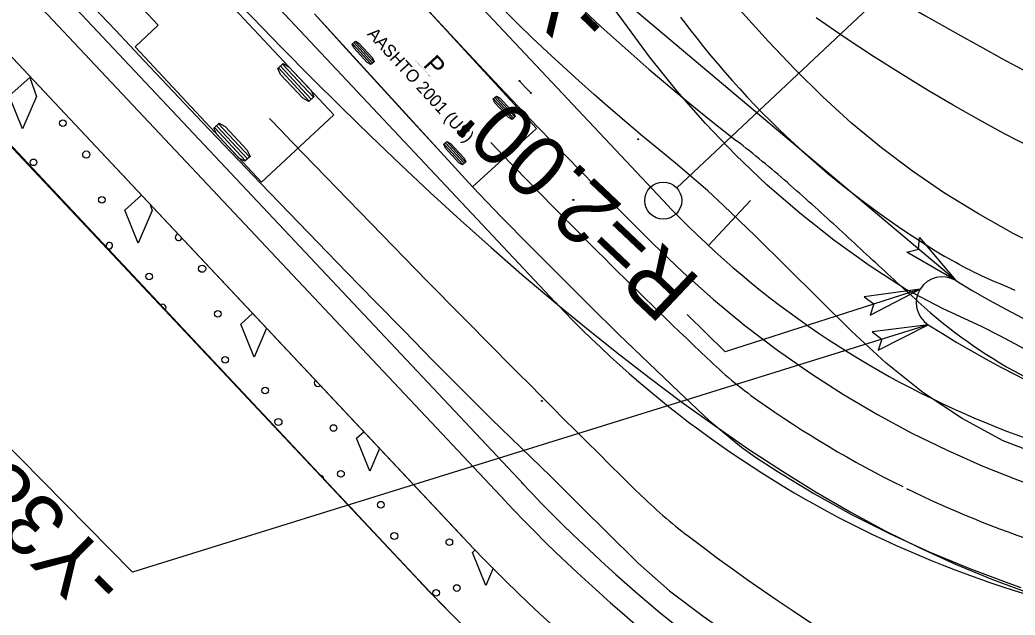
# Model space of a CAD drawing. Extents: x 1262642 to 1268358, y 767825 to 773481.
# Drawn here: x 1266608.5 to 1266689.1, y 772119 to 772167.3 of the extents above; entities that cross this region are included whole.
import ezdxf

# ---------------------------------------------------------------- set-up
doc = ezdxf.new("R2010")
doc.units = 0
for name, color, linetype in [('Prop Conc 2ft 6in Curb and Gutter', 7, 'Continuous'), ('Prop Conc 4in Sidewalk', 7, 'Continuous'), ('Prop Conc 5in Monolithic Keyed In Island', 7, 'Continuous'), ('Prop Dimension', 7, 'Continuous'), ('Prop Dimension Text', 7, 'Continuous'), ('Prop EOT', 7, 'Continuous'), ('Prop Horizontal Alignment', 7, 'Continuous'), ('Prop Horizontal Alignment Station Label', 7, 'Continuous'), ('Prop Horizontal Alignment Tick Small', 7, 'Continuous'), ('Prop Lane Lines', 7, 'Continuous'), ('Prop Shade Light', 7, 'Continuous'), ('Prop Shade Medium', 7, 'Continuous'), ('Prop Terminator CELL', 7, 'Continuous'), ('Scratch_Level_3', 7, 'Continuous')]:
    doc.layers.add(name, color=color, linetype=linetype)

msp = doc.modelspace()

# ---------------------------------------------------------------- linework, layer by layer
at = {"layer": 'Prop Conc 2ft 6in Curb and Gutter'}
for p, q in [((1266506.171, 772278.961), (1266647.877, 772128.235)), ((1266502.708, 772276.075), (1266644.436, 772125.326)), ((1266497.365, 772274.897), (1266640.835, 772121.856)), ((1266607.641, 772161.101), (1266609.327, 772162.599)), ((1266609.327, 772162.599), (1266609.851, 772161.065)), ((1266608.722, 772158.422), (1266607.641, 772161.101)), ((1266609.851, 772161.065), (1266608.722, 772158.422)), ((1266617.025, 772151.856), (1266618.37, 772153.051)), ((1266618.105, 772149.177), (1266617.025, 772151.856)), ((1266619.067, 772152.309), (1266619.235, 772151.819)), ((1266619.235, 772151.819), (1266618.105, 772149.177)), ((1266626.408, 772142.61), (1266627.377, 772143.47)), ((1266627.489, 772139.931), (1266626.408, 772142.61)), ((1266628.494, 772142.282), (1266627.489, 772139.931)), ((1266635.792, 772133.364), (1266636.384, 772133.89)), ((1266636.872, 772130.685), (1266635.792, 772133.364)), ((1266637.661, 772132.531), (1266636.872, 772130.685)), ((1266645.175, 772124.119), (1266645.41, 772124.327)), ((1266646.256, 772121.439), (1266645.175, 772124.119)), ((1266646.857, 772122.846), (1266646.256, 772121.439))]:
    msp.add_line(p, q, dxfattribs=at)
for centre, radius in [((1266611.995, 772158.895), 0.268), ((1266609.618, 772155.717), 0.268), ((1266613.896, 772156.346), 0.292), ((1266615.163, 772152.685), 0.268), ((1266623.279, 772147.101), 0.292), ((1266619.001, 772146.471), 0.268), ((1266624.546, 772143.44), 0.268), ((1266625.147, 772139.72), 0.268), ((1266628.385, 772137.225), 0.268), ((1266629.466, 772134.688), 0.285), ((1266633.93, 772134.194), 0.268), ((1266634.531, 772130.474), 0.268), ((1266637.768, 772127.98), 0.268), ((1266638.849, 772125.443), 0.285), ((1266643.313, 772124.948), 0.268), ((1266643.914, 772121.229), 0.268), ((1266642.238, 772120.84), 0.268)]:
    msp.add_circle(centre, radius, dxfattribs=at)
for centre, radius, start, end in [((1266621.379, 772149.649), 0.268, 102.32383, 344.14283), ((1266615.764, 772148.966), 0.268, 244.29036, 202.01228), ((1266620.082, 772143.934), 0.285, 321.32406, 124.97857), ((1266632.663, 772137.855), 0.292, 134.1808, 312.28587), ((1266632.854, 772130.085), 0.268, 359.4943, 86.80834), ((1266635.333, 772127.508), 0.18, 8.61303, 77.68961), ((1266740.242, 772215.4), 127, 223.23333, 257.86997), ((1266740.242, 772215.4), 131.5, 223.23333, 257.86997), ((1266740.242, 772215.4), 136.5, 223.25919, 257.86997)]:
    msp.add_arc(centre, radius, start, end, dxfattribs=at)
at = {"layer": 'Prop Conc 4in Sidewalk'}
for p, q in [((1266502.444, 772276.356), (1266644.598, 772125.153)), ((1266498.393, 772273.365), (1266640.956, 772121.728))]:
    msp.add_line(p, q, dxfattribs=at)
for radius in [131.5, 136.5]:
    msp.add_arc((1266740.242, 772215.4), radius, 223.23333, 257.86997, dxfattribs=at)
at = {"layer": 'Prop Conc 5in Monolithic Keyed In Island'}
for centre, radius, start, end in [((1266683.247, 772144.339), 2.105, 58.6153, 237.51858), ((1266725.486, 772213.579), 79.002, 238.6153, 274.54789), ((1266730.07, 772217.888), 89.293, 237.51857, 265.39188)]:
    msp.add_arc(centre, radius, start, end, dxfattribs=at)
at = {"layer": 'Prop Dimension'}
for p, q in [((1266684.313, 772146.162), (1266657.504, 772168.739)), ((1266681.461, 772145.452), (1266665.647, 772140.373)), ((1266682.115, 772142.563), (1266617.635, 772122.521))]:
    msp.add_line(p, q, dxfattribs=at)
at = {"layer": 'Prop Dimension Text'}
for p, q in [((1266577.146, 772163.559), (1266617.635, 772122.521)), ((1266662.582, 772143.392), (1266665.647, 772140.373))]:
    msp.add_line(p, q, dxfattribs=at)
at = {"layer": 'Prop EOT'}
msp.add_line((1266507.71, 772280.244), (1266649.334, 772129.605), dxfattribs=at)
for centre, radius, end in [((1266840.27, 772443.458), 318.091, 243.65317), ((1266740.242, 772215.4), 125, 257.86997)]:
    msp.add_arc(centre, radius, 223.23333, end, dxfattribs=at)
at = {"layer": 'Prop Horizontal Alignment'}
msp.add_line((1266456.698, 772369.54), (1266660.642, 772152.615), dxfattribs=at)
msp.add_arc((1266715.285, 772203.988), 75, 223.23333, 317.90382, dxfattribs=at)
at = {"layer": 'Prop Horizontal Alignment Station Label'}
msp.add_line((1266661.735, 772153.643), (1266683.114, 772173.743), dxfattribs=at)
msp.add_circle((1266660.642, 772152.615), 1.5, dxfattribs=at)
at = {"layer": 'Prop Horizontal Alignment Tick Small'}
msp.add_line((1266664.314, 772148.97), (1266667.712, 772152.638), dxfattribs=at)
at = {"layer": 'Prop Lane Lines'}
msp.add_line((1266516.453, 772288.464), (1266651.899, 772144.396), dxfattribs=at)
for centre, radius, start, end in [((1275047.307, 780021.225), 11427, 216.3674993, 223.5476842), ((1266715.285, 772203.988), 87, 223.23333, 266.78605)]:
    msp.add_arc(centre, radius, start, end, dxfattribs=at)
at = {"layer": 'Prop Shade Light'}
msp.add_arc((1266840.27, 772443.458), 318.091, 223.23333, 243.65317, dxfattribs=at)
at = {"layer": 'Prop Shade Medium'}
for centre, radius, start, end in [((1266683.247, 772144.339), 2.105, 58.6153, 237.51858), ((1266725.486, 772213.579), 79.002, 238.6153, 274.54789), ((1266730.07, 772217.888), 89.293, 237.51857, 265.39188)]:
    msp.add_arc(centre, radius, start, end, dxfattribs=at)
at = {"layer": 'Prop Terminator CELL'}
for points in [[(1266681.401, 772149.627), (1266684.343, 772146.136), (1266680.367, 772148.439), (1266681.322, 772148.68)], [(1266677.414, 772143.338), (1266681.461, 772145.452), (1266676.908, 772144.83), (1266677.7, 772144.244)], [(1266678.05, 772140.488), (1266682.117, 772142.564), (1266677.558, 772141.985), (1266678.345, 772141.391)]]:
    msp.add_lwpolyline(points, close=True, dxfattribs=at)
at = {"layer": 'Scratch_Level_3'}
for p, q in [((1266612.505, 772174.555), (1266619.732, 772166.823)), ((1266650.364, 772158.453), (1266637.54, 772172.472)), ((1266633.944, 772159.574), (1266623.701, 772170.533)), ((1266632.375, 772167.748), (1266645.199, 772153.728)), ((1266619.732, 772166.823), (1266617.857, 772165.07)), ((1266617.857, 772165.07), (1266628.099, 772154.111)), ((1266636.982, 772163.661), (1266635.463, 772165.321)), ((1266637.085, 772163.756), (1266635.567, 772165.416)), ((1266637.189, 772163.851), (1266635.671, 772165.511)), ((1266631.962, 772160.687), (1266629.458, 772163.366)), ((1266632.129, 772160.844), (1266629.626, 772163.523)), ((1266632.297, 772161), (1266629.793, 772163.679)), ((1266648.418, 772159.214), (1266646.899, 772160.874)), ((1266648.522, 772159.309), (1266647.003, 772160.969)), ((1266648.626, 772159.404), (1266647.107, 772161.064)), ((1266628.099, 772154.111), (1266633.944, 772159.574)), ((1266633.944, 772159.574), (1266633.944, 772159.574)), ((1266626.787, 772155.851), (1266624.283, 772158.529)), ((1266626.954, 772156.007), (1266624.451, 772158.686)), ((1266627.122, 772156.164), (1266624.618, 772158.842)), ((1266645.199, 772153.728), (1266650.364, 772158.453)), ((1266650.364, 772158.453), (1266650.364, 772158.453)), ((1266644.406, 772155.544), (1266642.887, 772157.204)), ((1266644.51, 772155.639), (1266642.991, 772157.299)), ((1266644.613, 772155.734), (1266643.095, 772157.394))]:
    msp.add_line(p, q, dxfattribs=at)
for points in [[(1266608.453, 772187.273), (1266610.806, 772184.78), (1266613.162, 772182.289), (1266615.521, 772179.801), (1266617.883, 772177.316), (1266620.249, 772174.835), (1266622.61, 772172.365), (1266624.977, 772169.902), (1266627.354, 772167.447), (1266629.742, 772165.004), (1266632.147, 772162.577), (1266634.57, 772160.169), (1266634.57, 772160.169), (1266636.947, 772157.848), (1266639.345, 772155.55), (1266641.768, 772153.278), (1266644.215, 772151.034), (1266646.69, 772148.821), (1266649.193, 772146.639), (1266651.726, 772144.492), (1266652.236, 772144.067)], [(1266690.415, 772149.243), (1266689.004, 772149.965), (1266686.172, 772151.541), (1266683.438, 772153.233), (1266680.84, 772155.01), (1266678.327, 772156.902), (1266675.902, 772158.905), (1266673.571, 772161.016), (1266671.336, 772163.229), (1266669.179, 772165.518), (1266667.051, 772167.834), (1266664.917, 772170.144), (1266662.784, 772172.456), (1266660.62, 772174.808), (1266658.396, 772177.225), (1266656.331, 772179.411)], [(1266606.895, 772176.432), (1266609.236, 772173.927), (1266611.578, 772171.423), (1266613.919, 772168.918), (1266613.919, 772168.918), (1266616.254, 772166.424), (1266618.595, 772163.935), (1266620.942, 772161.452), (1266623.296, 772158.975), (1266625.654, 772156.502), (1266628.017, 772154.035), (1266628.017, 772154.035), (1266630.332, 772151.629), (1266632.653, 772149.229), (1266634.978, 772146.833), (1266637.309, 772144.443), (1266639.646, 772142.058), (1266641.987, 772139.677), (1266644.334, 772137.303), (1266644.804, 772136.829)], [(1266687.975, 772141.631), (1266686.422, 772142.419), (1266683.317, 772143.851), (1266680.261, 772145.436), (1266677.315, 772147.349), (1266674.459, 772149.405), (1266671.699, 772151.589), (1266669.041, 772153.896), (1266666.49, 772156.322), (1266664.052, 772158.861), (1266661.731, 772161.508), (1266659.532, 772164.257), (1266657.461, 772167.102), (1266655.408, 772169.89), (1266653.17, 772172.416), (1266651.109, 772174.581)], [(1266637.54, 772172.472), (1266640.105, 772169.668), (1266642.673, 772166.867), (1266645.259, 772164.083), (1266647.865, 772161.318), (1266650.491, 772158.572), (1266650.491, 772158.572), (1266652.804, 772156.187), (1266655.131, 772153.817), (1266655.365, 772153.581)], [(1266665.534, 772152.219), (1266664.242, 772153.402), (1266662.94, 772154.552), (1266661.625, 772155.665), (1266660.296, 772156.746), (1266658.974, 772157.835), (1266657.663, 772158.937), (1266656.363, 772160.052), (1266655.074, 772161.18), (1266653.796, 772162.32), (1266652.53, 772163.473), (1266651.274, 772164.638), (1266650.031, 772165.815), (1266648.799, 772167.005), (1266647.579, 772168.207)], [(1266632.375, 772167.748), (1266634.926, 772164.932), (1266637.493, 772162.129), (1266640.069, 772159.336), (1266642.634, 772156.532), (1266645.199, 772153.728), (1266645.199, 772153.728), (1266645.199, 772153.728), (1266647.522, 772151.304), (1266649.88, 772148.901), (1266650.117, 772148.661)], [(1266662.255, 772167.21), (1266662.055, 772167.477)], [(1266690.394, 772156.947), (1266688.288, 772158.04), (1266686.194, 772159.177), (1266684.124, 772160.351), (1266682.05, 772161.576), (1266679.914, 772162.886), (1266677.69, 772164.302), (1266675.393, 772165.817), (1266673.036, 772167.425)], [(1266648.997, 772162.313), (1266649.222, 772162.067), (1266649.449, 772161.822), (1266649.677, 772161.58), (1266649.908, 772161.339)], [(1266681.795, 772143.981), (1266681.546, 772144.203), (1266681.298, 772144.426), (1266681.05, 772144.648), (1266680.803, 772144.872), (1266680.555, 772145.095), (1266680.308, 772145.319), (1266680.062, 772145.543), (1266679.816, 772145.768), (1266679.569, 772145.993), (1266679.324, 772146.218), (1266679.078, 772146.443), (1266678.833, 772146.669), (1266678.587, 772146.895), (1266678.342, 772147.121), (1266678.097, 772147.347), (1266677.853, 772147.573), (1266677.608, 772147.799), (1266677.363, 772148.026), (1266677.118, 772148.252), (1266676.874, 772148.478), (1266676.629, 772148.705), (1266676.385, 772148.931), (1266676.14, 772149.158), (1266675.895, 772149.384), (1266675.65, 772149.61), (1266675.405, 772149.836), (1266675.16, 772150.062), (1266674.915, 772150.288), (1266674.669, 772150.513), (1266674.424, 772150.738), (1266674.178, 772150.963), (1266673.931, 772151.188), (1266673.685, 772151.413), (1266673.438, 772151.637), (1266673.191, 772151.86), (1266672.944, 772152.084), (1266672.696, 772152.307), (1266672.448, 772152.529), (1266672.199, 772152.751), (1266671.95, 772152.973), (1266671.701, 772153.194), (1266671.451, 772153.415), (1266671.2, 772153.635), (1266670.949, 772153.854), (1266670.698, 772154.073), (1266670.446, 772154.291), (1266670.193, 772154.508), (1266669.94, 772154.725), (1266669.686, 772154.941), (1266669.431, 772155.156), (1266669.176, 772155.371), (1266668.92, 772155.584), (1266668.664, 772155.797), (1266668.406, 772156.009), (1266668.148, 772156.22), (1266667.89, 772156.43), (1266667.63, 772156.639), (1266667.37, 772156.847), (1266667.108, 772157.054), (1266666.846, 772157.26), (1266666.583, 772157.465)], [(1266655.365, 772153.581), (1266657.474, 772151.462), (1266659.832, 772149.124), (1266662.227, 772146.823), (1266664.701, 772144.608), (1266667.262, 772142.495), (1266669.904, 772140.489), (1266672.574, 772138.626), (1266673.64, 772137.925)], [(1266691.649, 772131.822), (1266688.188, 772133.151), (1266684.864, 772134.954), (1266681.685, 772137.075), (1266678.691, 772139.452), (1266675.907, 772142.037), (1266673.254, 772144.649), (1266670.661, 772147.238), (1266668.098, 772149.771), (1266665.534, 772152.219)], [(1266650.117, 772148.661), (1266652.254, 772146.512), (1266654.643, 772144.139), (1266657.048, 772141.782), (1266659.467, 772139.44), (1266661.901, 772137.113), (1266664.352, 772134.806), (1266666.98, 772132.64), (1266668.115, 772131.843)], [(1266687.941, 772145.866), (1266687.633, 772145.995), (1266687.327, 772146.126), (1266687.021, 772146.259), (1266686.717, 772146.396), (1266686.414, 772146.535), (1266686.113, 772146.677), (1266685.813, 772146.822), (1266685.514, 772146.97), (1266685.217, 772147.121), (1266684.921, 772147.276), (1266684.627, 772147.433), (1266684.335, 772147.593), (1266684.045, 772147.757), (1266683.756, 772147.923), (1266683.469, 772148.093)], [(1266689.164, 772145.337), (1266688.86, 772145.472), (1266688.554, 772145.605), (1266688.248, 772145.736), (1266687.941, 772145.866)], [(1266652.236, 772144.067), (1266654.289, 772142.381), (1266656.882, 772140.309), (1266659.505, 772138.278), (1266662.157, 772136.294), (1266664.84, 772134.361), (1266667.285, 772132.672)], [(1266724.039, 772133.273), (1266721.735, 772132.757), (1266717.922, 772132.144), (1266714.085, 772131.937), (1266710.249, 772132.181), (1266706.467, 772132.872), (1266702.791, 772134.001), (1266699.271, 772135.546), (1266695.913, 772137.289), (1266692.681, 772139.068), (1266689.532, 772140.803), (1266687.975, 772141.631)], [(1266664.195, 772139.861), (1266664.436, 772139.631), (1266664.68, 772139.404), (1266664.925, 772139.178), (1266665.172, 772138.954), (1266665.421, 772138.732), (1266665.672, 772138.513), (1266665.924, 772138.295), (1266666.179, 772138.08), (1266666.436, 772137.867), (1266666.694, 772137.657), (1266666.955, 772137.449), (1266667.217, 772137.244), (1266667.482, 772137.041), (1266667.749, 772136.841), (1266668.018, 772136.644), (1266668.288, 772136.45)], [(1266673.64, 772137.925), (1266675.253, 772136.907), (1266677.993, 772135.295), (1266680.792, 772133.79), (1266683.647, 772132.394), (1266686.546, 772131.112), (1266689.482, 772129.947), (1266692.46, 772128.896), (1266693.361, 772128.603)], [(1266644.804, 772136.829), (1266646.697, 772134.944), (1266649.103, 772132.625), (1266651.497, 772130.296), (1266653.865, 772127.943), (1266656.238, 772125.594), (1266658.378, 772123.485)], [(1266667.285, 772132.672), (1266667.558, 772132.488), (1266670.292, 772130.697), (1266673.026, 772129.006), (1266675.798, 772127.398), (1266678.614, 772125.876), (1266681.474, 772124.45), (1266684.378, 772123.125), (1266687.324, 772121.911), (1266690.312, 772120.812), (1266693.032, 772119.925)], [(1266668.115, 772131.843), (1266669.87, 772130.699), (1266672.853, 772128.884), (1266675.905, 772127.187), (1266679.022, 772125.609), (1266682.185, 772124.155), (1266685.388, 772122.827), (1266688.641, 772121.622), (1266689.625, 772121.285)], [(1266658.18, 772129.376), (1266658.417, 772129.141), (1266658.655, 772128.908), (1266658.895, 772128.677), (1266659.137, 772128.447), (1266659.38, 772128.219), (1266659.625, 772127.993), (1266659.871, 772127.769), (1266660.119, 772127.546), (1266660.368, 772127.325), (1266660.62, 772127.106), (1266660.872, 772126.888), (1266661.127, 772126.673), (1266661.383, 772126.46), (1266661.641, 772126.248), (1266661.9, 772126.039), (1266662.161, 772125.832), (1266662.424, 772125.627), (1266662.688, 772125.424)], [(1266658.378, 772123.485), (1266658.618, 772123.252), (1266661.141, 772121.016), (1266663.875, 772118.961), (1266666.687, 772116.985), (1266669.539, 772115.067), (1266672.43, 772113.209), (1266675.359, 772111.411), (1266678.325, 772109.673), (1266681.326, 772107.997), (1266684.055, 772106.541)]]:
    msp.add_lwpolyline(points, dxfattribs=at)
for points in [[(1266637.215, 772163.874), (1266636.956, 772163.637), (1266636.665, 772163.798), (1266635.572, 772164.994), (1266635.437, 772165.297), (1266635.696, 772165.534), (1266635.987, 772165.373), (1266637.08, 772164.178)], [(1266632.338, 772161.039), (1266631.92, 772160.648), (1266631.444, 772160.906), (1266629.641, 772162.835), (1266629.417, 772163.327), (1266629.835, 772163.718), (1266630.311, 772163.46), (1266632.114, 772161.532)], [(1266648.651, 772159.427), (1266648.392, 772159.19), (1266648.102, 772159.352), (1266647.008, 772160.547), (1266646.874, 772160.851), (1266647.133, 772161.088), (1266647.423, 772160.927), (1266648.517, 772159.731)], [(1266627.163, 772156.202), (1266626.745, 772155.812), (1266626.269, 772156.069), (1266624.466, 772157.998), (1266624.242, 772158.491), (1266624.66, 772158.881), (1266625.136, 772158.624), (1266626.939, 772156.695)], [(1266644.639, 772155.757), (1266644.38, 772155.521), (1266644.09, 772155.682), (1266642.996, 772156.877), (1266642.862, 772157.181), (1266643.121, 772157.418), (1266643.411, 772157.257), (1266644.505, 772156.061)]]:
    msp.add_lwpolyline(points, close=True, dxfattribs=at)
for centre in [(1266648.997, 772162.313), (1266649.908, 772161.339), (1266649.908, 772161.339), (1266658.605, 772157.589), (1266658.605, 772157.589), (1266653.358, 772152.67), (1266653.358, 772152.67), (1266650.81, 772136.393), (1266650.81, 772136.393)]:
    msp.add_circle(centre, 0.0417, dxfattribs=at)
for centre, radius, start, end in [((1266770.294, 772291.604), 169.556, 218.19483, 232.29011), ((1266721.234, 772211.333), 73.657, 216.80057, 239.15536), ((1267763.528, 773246.763), 1571.734, 223.780725, 225.310317), ((1267022.507, 772516.908), 520.146, 223.73331, 226.45948), ((1266709.044, 772174.614), 40.999, 228.34586, 242.4992), ((1266717.965, 772206.431), 85.82, 234.63087, 243.7787), ((1266718.246, 772206.626), 86.119, 243.88946, 259.79186), ((1266761.141, 772254.43), 162.283, 232.6506, 249.30211)]:
    msp.add_arc(centre, radius, start, end, dxfattribs=at)

# ---------------------------------------------------------------- texts
at = {"layer": 'Prop Dimension'}
msp.add_text("R=2.00'", height=5, rotation=136.59024, dxfattribs=at).set_placement((1266663.831, 772146.12))
at = {"layer": 'Prop Dimension Text'}
for s, p in [('-Y38SW- +19.21', (1266656.856, 772167.656)), ('-Y38SW- +18.91', (1266617.472, 772122.094))]:
    msp.add_text(s, height=5, rotation=135.42387, dxfattribs=at).set_placement(p)
at = {"layer": 'Scratch_Level_3'}
for s, height, p in [('AASHTO 2001 (US)', 1, (1266636.607, 772166.077)), ('(c) 2016 Transoft Solutions, Inc. All rights reserved.', 0.06, (1266640.522, 772163.982)), ('P', 1.5, (1266641.12, 772163.55))]:
    msp.add_text(s, height=height, rotation=312.44899, dxfattribs=at).set_placement(p)

doc.saveas('drawing.dxf')
